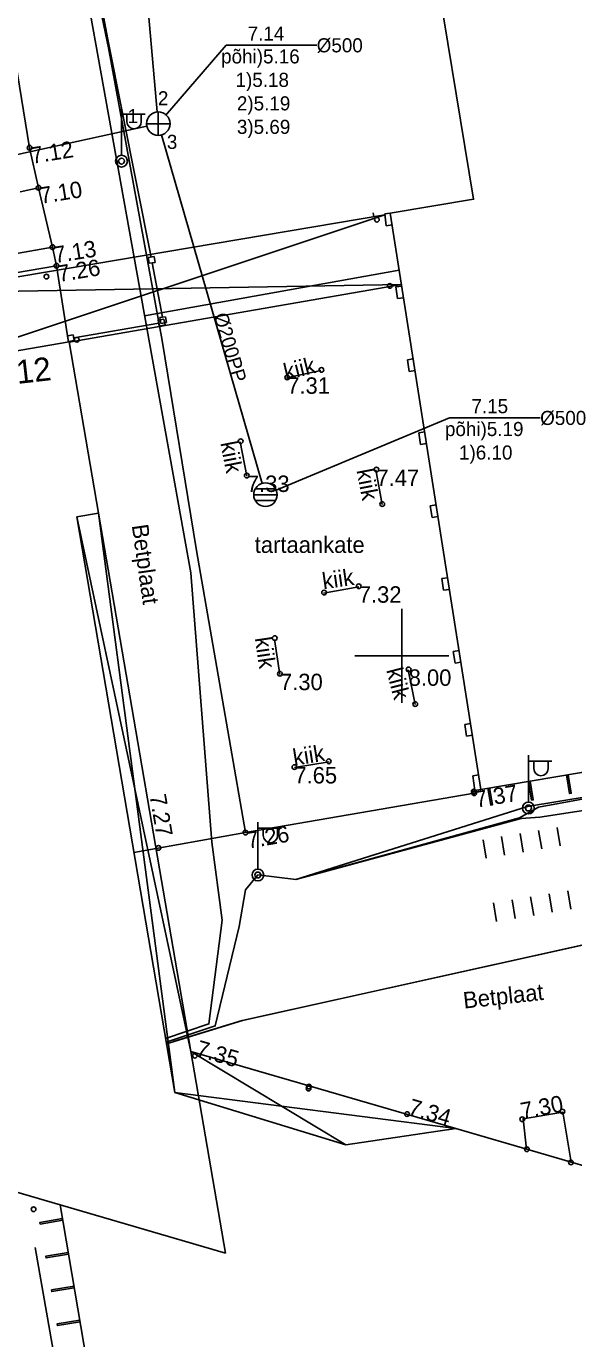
# Model space of a CAD drawing. Extents: x 473307 to 473719, y 6532843 to 6533381.
# Drawn here: x 473584 to 473607.3, y 6532970.9 to 6533026.8 of the extents above; entities that cross this region are included whole.
import ezdxf

# ---------------------------------------------------------------- set-up
doc = ezdxf.new("R2010")
doc.units = 0
for name, color, linetype in [('AED', 7, 'Continuous'), ('Default', 7, 'Continuous'), ('HOONE', 7, 'Continuous'), ('HOONEDET', 7, 'Continuous'), ('KORGUS', 7, 'Continuous'), ('MPKAABEL', 7, 'Continuous'), ('POST', 7, 'Continuous'), ('RAJATIS', 7, 'Continuous'), ('SITRASS', 7, 'Continuous'), ('SKKAEV', 7, 'Continuous'), ('SKKAEV_NR', 7, 'Continuous'), ('SKTRASS', 7, 'Continuous'), ('SKTRASS_TEKST', 7, 'Continuous'), ('TEE', 7, 'Continuous'), ('VORK', 7, 'Continuous')]:
    doc.layers.add(name, color=color, linetype=linetype)

# ---------------------------------------------------------------- blocks, each defined once
blk = doc.blocks.new('VARPOS')
at = {"layer": 'Default'}
for p, q in [((-0.25, 0.25), (-0.25, -0.25)), ((-0.25, 0.25), (0.25, 0.25)), ((0.25, 0.25), (0.25, -0.25)), ((-0.25, -0.25), (0.25, -0.25))]:
    blk.add_line(p, q, dxfattribs=at)
blk = doc.blocks.new('MEPOST')
at = {"layer": 'Default'}
blk.add_circle((0, 0), 0.5, dxfattribs=at)
for start, end in [(0, 180), (180, 0)]:
    blk.add_arc((0, 0), 0.25, start, end, dxfattribs=at)
blk = doc.blocks.new('VAPOST')
at = {"layer": 'Default'}
for p, q in [((0, 0.5), (0, 4.5)), ((0, 4), (2, 4)), ((0.45, 3.36), (0.45, 4)), ((1.68, 3.36), (1.68, 4))]:
    blk.add_line(p, q, dxfattribs=at)
blk.add_arc((1.07, 3.36), 0.613, 180, 0, dxfattribs=at)
blk = doc.blocks.new('REKAEV')
at = {"layer": 'Default'}
for p, q in [((-1, 0), (1, 0)), ((0.86, 0.5), (-0.86, 0.5)), ((0.86, -0.5), (-0.86, -0.5))]:
    blk.add_line(p, q, dxfattribs=at)
blk.add_circle((0, 0), 1, dxfattribs=at)
blk = doc.blocks.new('KAKAEV')
at = {"layer": 'Default'}
for p, q in [((-1, 0), (1, 0)), ((0, -1), (0, 1))]:
    blk.add_line(p, q, dxfattribs=at)
blk.add_circle((0, 0), 1, dxfattribs=at)
blk = doc.blocks.new('VKORIS')
at = {"layer": 'Default'}
for p, q in [((0, 4), (0, -4)), ((-4, 0), (4, 0))]:
    blk.add_line(p, q, dxfattribs=at)

msp = doc.modelspace()

# ---------------------------------------------------------------- linework, layer by layer
at = {"layer": 'AED'}
for points in [[(473589.326, 6533016.984), (473587.477, 6533026.249), (473586.562, 6533031.174), (473585.527, 6533035.229), (473580.26, 6533043.389), (473579.539, 6533044.817), (473577.795, 6533055.452)], [(473589.37, 6533016.738), (473589.816, 6533014.424)], [(473586.032, 6533013.551), (473589.651, 6533014.169)]]:
    msp.add_lwpolyline(points, dxfattribs=at)
at = {"layer": 'HOONE'}
for p in [(473591.02, 6532983.164), (473585.455, 6532976.623)]:
    msp.add_line(p, (473592.497, 6532974.566), dxfattribs=at)
for points in [[(473618.421, 6532996.851), (473614.923, 6533017.718), (473616.359, 6533017.954), (473611.949, 6533045.219), (473599.157, 6533043.085), (473599.77, 6533039.408), (473600.209, 6533036.749), (473601.229, 6533030.585), (473603.062, 6533019.443), (473599.51, 6533018.858), (473603.372, 6532994.32), (473618.421, 6532996.851)], [(473580.042, 6533012.374), (473579.602, 6533015.453), (473599.285, 6533018.774)], [(473599.285, 6533018.774), (473580.042, 6533012.374)], [(473599.279, 6533018.82), (473599.51, 6533018.858)], [(473599.279, 6533018.82), (473599.339, 6533018.318)], [(473599.339, 6533018.318), (473599.589, 6533018.357)], [(473579.602, 6533015.453), (473599.989, 6533015.81)], [(473599.989, 6533015.81), (473585.834, 6533013.354)], [(473599.749, 6533015.711), (473599.999, 6533015.75)], [(473599.749, 6533015.711), (473599.826, 6533015.213)], [(473599.826, 6533015.213), (473600.077, 6533015.253)], [(473600.238, 6533012.606), (473600.488, 6533012.646)], [(473600.238, 6533012.606), (473600.315, 6533012.108)], [(473600.315, 6533012.108), (473600.566, 6533012.148)], [(473600.726, 6533009.502), (473600.976, 6533009.541)], [(473600.726, 6533009.502), (473600.803, 6533009.004)], [(473600.803, 6533009.004), (473601.055, 6533009.043)], [(473601.215, 6533006.397), (473601.465, 6533006.436)], [(473601.215, 6533006.397), (473601.292, 6533005.899)], [(473602.305, 6532979.874), (473591.02, 6532983.164), (473587.084, 6533006.076)], [(473601.292, 6533005.899), (473601.543, 6533005.938)], [(473601.704, 6533003.292), (473601.954, 6533003.331)], [(473601.704, 6533003.292), (473601.781, 6533002.794)], [(473601.781, 6533002.794), (473602.032, 6533002.834)], [(473602.192, 6533000.187), (473602.442, 6533000.227)], [(473602.192, 6533000.187), (473602.269, 6532999.689)], [(473602.269, 6532999.689), (473602.521, 6532999.729)], [(473602.681, 6532997.083), (473602.931, 6532997.122)], [(473602.681, 6532997.083), (473602.758, 6532996.585)], [(473602.758, 6532996.585), (473603.009, 6532996.624)], [(473603.022, 6532994.892), (473603.276, 6532994.932)], [(473603.117, 6532994.278), (473603.022, 6532994.892)], [(473603.117, 6532994.278), (473603.372, 6532994.32)], [(473601.982, 6532979.826), (473601.962, 6532979.824)]]:
    msp.add_lwpolyline(points, dxfattribs=at)
msp.add_lwpolyline([(473585.831, 6533013.369), (473574.881, 6533011.486), (473566.132, 6533009.962), (473540.511, 6533005.576), (473543.395, 6532988.91), (473585.455, 6532976.623), (473588.828, 6532956.753), (473587.886, 6532956.595), (473589.164, 6532949.286), (473629.221, 6532956.166), (473626.335, 6532972.834), (473619.836, 6532974.765), (473602.305, 6532979.874), (473597.625, 6532979.18), (473590.334, 6532981.418), (473586.157, 6533005.917), (473587.084, 6533006.076)], close=True, dxfattribs=at)
at = {"layer": 'HOONEDET'}
for p, q in [((473591.02, 6532983.164), (473586.157, 6533005.917)), ((473587.084, 6533006.076), (473590.334, 6532981.418)), ((473597.625, 6532979.18), (473591.02, 6532983.164)), ((473590.334, 6532981.418), (473602.305, 6532979.874))]:
    msp.add_line(p, q, dxfattribs=at)
for points in [[(473605.394, 6532994.66), (473605.528, 6532993.861), (473605.598, 6532993.873), (473605.463, 6532994.672)], [(473607.017, 6532994.933), (473607.15, 6532994.14), (473607.22, 6532994.152), (473607.086, 6532994.945)], [(473603.668, 6532994.37), (473603.789, 6532993.647), (473603.859, 6532993.659), (473603.737, 6532994.382)], [(473585.565, 6532975.976), (473584.604, 6532975.813), (473584.592, 6532975.882), (473585.553, 6532976.045)], [(473585.81, 6532974.533), (473584.851, 6532974.371), (473584.839, 6532974.44), (473585.798, 6532974.602)], [(473586.053, 6532973.098), (473585.097, 6532972.936), (473585.085, 6532973.005), (473586.042, 6532973.167)], [(473586.298, 6532971.655), (473585.334, 6532971.492), (473585.322, 6532971.561), (473586.287, 6532971.724)]]:
    msp.add_lwpolyline(points, dxfattribs=at)
at = {"layer": 'KORGUS'}
for centre in [(473584.149, 6533021.64), (473584.525, 6533019.936), (473598.941, 6533018.575), (473585.125, 6533017.41), (473585.294, 6533016.611), (473584.867, 6533016.149), (473599.486, 6533015.757), (473586.159, 6533013.459), (473595.121, 6533011.861), (473596.581, 6533012.178), (473593.14, 6533009.143), (473598.92, 6533007.937), (473593.401, 6533007.681), (473599.171, 6533006.468), (473598.168, 6533002.966), (473596.693, 6533002.7), (473594.592, 6533000.758), (473594.814, 6532999.243), (473600.294, 6532999.428), (473600.574, 6532997.951), (473595.426, 6532995.27), (473596.894, 6532995.513), (473603.066, 6532994.225), (473603.086, 6532994.155), (473593.34, 6532992.481), (473589.64, 6532991.824), (473591.19, 6532982.981), (473596.03, 6532981.581), (473596.049, 6532981.667), (473600.227, 6532980.493), (473606.84, 6532980.604), (473605.135, 6532980.274), (473605.332, 6532978.998), (473607.206, 6532978.437), (473584.322, 6532976.44)]:
    msp.add_circle(centre, 0.1, dxfattribs=at)
at = {"layer": 'MPKAABEL'}
for points in [[(473589.942, 6532983.714), (473591.786, 6532984.334), (473592.352, 6532988.75), (473591.917, 6532992.074), (473591.014, 6533003.533), (473585.864, 6533032.22), (473579.145, 6533044.281), (473578.575, 6533045.974), (473579.606, 6533048.994), (473580.641, 6533050.075), (473587.569, 6533052.134)], [(473620.617, 6533046.296), (473621.149, 6533045.558), (473623.184, 6533033.982), (473622.885, 6533033.671), (473623.161, 6533033.456), (473625.425, 6533021.422), (473625.127, 6533020.991), (473625.392, 6533020.733), (473627.527, 6533008.94), (473627.41, 6533008.689), (473627.547, 6533008.477), (473629.153, 6532997.882), (473628.743, 6532997.831), (473628.458, 6532997.764), (473616.426, 6532995.506), (473605.82, 6532993.566), (473605.008, 6532993.105), (473595.487, 6532990.476)], [(473621.156, 6533046.272), (473623.63, 6533034.104), (473627.965, 6533008.739), (473629.773, 6532998.346), (473629.672, 6532997.664), (473629.313, 6532997.141), (473629.074, 6532996.947), (473617.704, 6532994.967), (473617.505, 6532995.424), (473617.231, 6532994.874), (473616.914, 6532994.828), (473605.877, 6532993.134), (473605.088, 6532993.085), (473595.487, 6532990.476)], [(473599.893, 6533016.424), (473589.049, 6533014.478)], [(473640.808, 6532999.44), (473629.396, 6532997.595), (473617.328, 6532995.569), (473605.359, 6532993.589), (473595.487, 6532990.476)], [(473595.487, 6532990.476), (473593.873, 6532990.674), (473593.344, 6532990.039), (473593.074, 6532988.477), (473592.054, 6532984.245), (473589.97, 6532983.549)], [(473589.982, 6532983.479), (473593.223, 6532984.475), (473614.824, 6532989.275), (473615.996, 6532988.691), (473617.05, 6532989.487), (473632.11, 6532989.067), (473634.265, 6532985.165), (473634.709, 6532982.151), (473635.055, 6532979.491), (473635.143, 6532979.077), (473636.479, 6532976.519), (473639.052, 6532971.522), (473639.321, 6532970.77), (473636.63, 6532971.595), (473634.35, 6532972.351), (473634.746, 6532971.823), (473635.044, 6532970.343), (473635.389, 6532970.07), (473641.031, 6532968.378), (473642.184, 6532969.946)]]:
    msp.add_lwpolyline(points, dxfattribs=at)
at = {"layer": 'RAJATIS'}
for points in [[(473595.091, 6533011.836), (473596.555, 6533012.151)], [(473593.124, 6533009.113), (473593.406, 6533007.659)], [(473598.89, 6533007.922), (473599.171, 6533006.443)], [(473596.67, 6533002.671), (473598.166, 6533002.939)], [(473594.804, 6532999.212), (473594.583, 6533000.704)], [(473600.267, 6532999.404), (473600.57, 6532997.929)], [(473596.911, 6532995.491), (473595.435, 6532995.252)], [(473604.382, 6532991.519), (473604.251, 6532992.308)], [(473605.171, 6532991.65), (473605.04, 6532992.439)], [(473605.961, 6532991.781), (473605.83, 6532992.57)], [(473606.75, 6532991.912), (473606.619, 6532992.701)], [(473603.593, 6532991.388), (473603.462, 6532992.177)], [(473604.04, 6532988.695), (473603.91, 6532989.485)], [(473604.829, 6532988.825), (473604.7, 6532989.614)], [(473605.619, 6532988.955), (473605.489, 6532989.744)], [(473606.408, 6532989.084), (473606.278, 6532989.874)], [(473607.198, 6532989.214), (473607.068, 6532990.004)]]:
    msp.add_lwpolyline(points, dxfattribs=at)
at = {"layer": 'SITRASS'}
msp.add_lwpolyline([(473590.274, 6532983.589), (473593.199, 6532984.483), (473615.964, 6532989.523), (473632.286, 6532988.799), (473642.743, 6532988.547), (473655.555, 6532988.13)], dxfattribs=at)
at = {"layer": 'SKKAEV_NR'}
for points in [[(473589.938, 6533023.016), (473592.523, 6533025.999), (473596.378, 6533025.999)], [(473594.658, 6533007.057), (473602.04, 6533010.134), (473605.895, 6533010.134)]]:
    msp.add_lwpolyline(points, dxfattribs=at)
at = {"layer": 'SKTRASS'}
for points in [[(473587.953, 6533041.685), (473589.587, 6533023.16)], [(473572.149, 6533018.838), (473589.143, 6533022.555)], [(473589.77, 6533022.182), (473594.057, 6533007.345)]]:
    msp.add_lwpolyline(points, dxfattribs=at)
at = {"layer": 'TEE'}
msp.add_line((473598.783, 6533018.864), (473598.812, 6533018.694), dxfattribs=at)
for points in [[(473588.591, 6532991.638), (473593.34, 6532992.481), (473591.254, 6533004.496), (473589.795, 6533013.429), (473587.512, 6533025.896), (473586.16, 6533032.358), (473584.645, 6533037.171), (473582.585, 6533040.392), (473579.391, 6533044.452), (473577.651, 6533055.031)], [(473584.525, 6533019.936), (473584.149, 6533021.64), (473582.327, 6533032.76), (473579.699, 6533037.965), (473575.769, 6533043.341), (473573.951, 6533054.606), (473567.843, 6533044.573), (473562.514, 6533035.841), (473557.652, 6533027.859), (473551.671, 6533018.048), (473551.004, 6533017.017)], [(473583.745, 6533019.767), (473584.525, 6533019.936)], [(473585.125, 6533017.41), (473584.525, 6533019.936)], [(473585.125, 6533017.41), (473578.353, 6533016.212)], [(473585.294, 6533016.611), (473585.125, 6533017.41)], [(473585.814, 6533013.366), (473585.294, 6533016.611), (473579.55, 6533015.627), (473580.094, 6533012.382)], [(473593.34, 6532992.481), (473603.086, 6532994.155), (473603.054, 6532994.267)], [(473605.308, 6532978.999), (473605.169, 6532980.292), (473606.867, 6532980.57), (473607.215, 6532978.443)], [(473628.659, 6532961.442), (473629.682, 6532955.878), (473626.442, 6532955.32), (473616.532, 6532953.615), (473614.764, 6532953.342), (473608.106, 6532952.185), (473599.94, 6532950.776), (473595.6, 6532950.065), (473591.811, 6532949.391), (473588.835, 6532948.995), (473588.198, 6532952.676), (473587.089, 6532959.111), (473586.081, 6532965.174), (473584.393, 6532974.809)]]:
    msp.add_lwpolyline(points, dxfattribs=at)

# ---------------------------------------------------------------- block references
at = {"layer": 'AED'}
for p, xscale, yscale, rotation in [((473589.35, 6533016.861), 0.5, 0.5, -80.96545926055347), ((473589.774, 6533014.192), 0.5, 0.5, -169.22933941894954), ((473589.837, 6533014.301), 0.4999999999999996, 0.4999999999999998, 99.48072677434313), ((473585.909, 6533013.531), 0.4999999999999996, 0.4999999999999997, 9.346181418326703)]:
    msp.add_blockref('VARPOS', p, dxfattribs=dict(at, xscale=xscale, yscale=yscale, rotation=rotation))
at = {"layer": 'POST', "xscale": 0.5, "yscale": 0.5}
for name, p in [('VAPOST', (473588.066, 6533021.067)), ('MEPOST', (473588.066, 6533021.067)), ('VAPOST', (473605.394, 6532993.525)), ('MEPOST', (473605.394, 6532993.525)), ('VAPOST', (473593.873, 6532990.674)), ('MEPOST', (473593.873, 6532990.674))]:
    msp.add_blockref(name, p, dxfattribs=at)
at = {"layer": 'SKKAEV', "xscale": 0.5, "yscale": 0.5}
for name, p in [('KAKAEV', (473589.631, 6533022.662)), ('REKAEV', (473594.196, 6533006.865))]:
    msp.add_blockref(name, p, dxfattribs=at)
at = {"layer": 'VORK', "xscale": 0.5, "yscale": 0.5}
msp.add_blockref('VKORIS', (473600, 6533000), dxfattribs=at)

# ---------------------------------------------------------------- texts
at = {"layer": 'HOONE'}
msp.add_text('12', height=1, rotation=6.4003, dxfattribs=at).set_placement((473583.636, 6533011.58))
at = {"layer": 'KORGUS'}
for s, rotation, p in [('7.12', 9.2803, (473584.262, 6533020.949)), ('7.10', 9.2803, (473584.638, 6533019.245)), ('7.13', 9.2803, (473585.238, 6533016.719)), ('7.26', 9.2803, (473585.407, 6533015.92)), ('7.37', 9.5441, (473603.182, 6532993.535)), ('7.27', 279.7482, (473589.256, 6532994.058)), ('7.26', 9.7462, (473593.458, 6532991.791)), ('7.35', 343.8672, (473591.19, 6532982.981)), ('7.34', 343.6773, (473600.227, 6532980.493)), ('7.30', 10.9541, (473605.135, 6532980.274))]:
    msp.add_text(s, height=0.7, rotation=rotation, dxfattribs=at).set_placement(p)
for s, p in [('7.31', (473595.121, 6533011.161)), ('7.47', (473598.92, 6533007.237)), ('7.33', (473593.401, 6533006.981)), ('7.32', (473598.168, 6533002.266)), ('7.30', (473594.814, 6532998.543)), ('8.00', (473600.294, 6532998.728)), ('7.65', (473595.426, 6532994.57))]:
    msp.add_text(s, height=0.7, dxfattribs=at).set_placement(p)
at = {"layer": 'RAJATIS'}
for rotation, p in [(13.8399, (473595.065, 6533011.737)), (280.9869, (473592.273, 6533009.071)), (280.7768, (473598.071, 6533007.903)), (8.1193, (473596.663, 6533002.835)), (278.3772, (473593.74, 6533000.761)), (284.489, (473599.336, 6532999.403)), (9.1903, (473595.422, 6532995.324))]:
    msp.add_text('kiik', height=0.7, rotation=rotation, dxfattribs=at).set_placement(p)
at = {"layer": 'SKKAEV_NR'}
for s, p in [('7.14', (473593.437, 6533026.199)), ('põhi)5.16', (473592.308, 6533025.227)), ('%%C500', (473596.378, 6533025.699)), ('1)5.18', (473592.922, 6533024.227)), ('2', (473589.615, 6533023.442)), ('2)5.19', (473592.979, 6533023.227)), ('1', (473588.325, 6533022.686)), ('3)5.69', (473592.979, 6533022.227)), ('3', (473589.996, 6533021.588)), ('7.15', (473602.968, 6533010.334)), ('%%C500', (473605.895, 6533009.834)), ('põhi)5.19', (473601.839, 6533009.362)), ('1)6.10', (473602.439, 6533008.362))]:
    msp.add_text(s, height=0.6, dxfattribs=at).set_placement(p)
at = {"layer": 'SKTRASS_TEKST'}
msp.add_text('%%C200PP', height=0.6, rotation=286.1182, dxfattribs=at).set_placement((473591.986, 6533014.512))
at = {"layer": 'TEE'}
for rotation, p in [(278.0408, (473588.501, 6533005.559)), (6.29, (473602.653, 6532984.983))]:
    msp.add_text('Betplaat', height=0.7, rotation=rotation, dxfattribs=at).set_placement(p)
msp.add_text('tartaankate', height=0.7, dxfattribs=at).set_placement((473593.739, 6533004.386))

doc.saveas('drawing.dxf')
